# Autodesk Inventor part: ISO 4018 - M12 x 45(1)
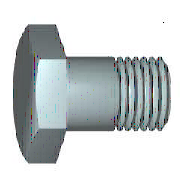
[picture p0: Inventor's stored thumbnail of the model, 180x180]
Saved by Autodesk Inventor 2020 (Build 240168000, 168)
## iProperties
Created: 2019-01
Part Number: ISO 4018 - M12 x 45(1)
Material: Ocel
Description: Šrouby se šestihrannou hlavou se závitem k hlavě. Výrobní třída C
Document SubType Name: Modeling
Standard: ISO 4018
Designer: doma
Standard Revision: Fourth edition 2011-04-01
Standards Organization: ISO
Language: cs-CZ
Size Designation: M12 x 45
Categories: <MemberInstance><Categories><Category DisplayName="Spojovací materiál" InternalName="e4da775c-781d-43d5-af7c-5136215cf5a6" Mnemonic="FSTN"><Category DisplayName
Density: 7.85 g/cm^3
Appearance: Plech
Mass: 56.3374 g
Surface Area: 26.8228 cm^2
Volume: 7.17674 cm^3
IsCustomPart: 0
Author: doma
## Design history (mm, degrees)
node "WorkPlane1"
node "WorkPoint1"
node "MSC_A1"
node "MSC_PF1"
node "MSC_PT1"
body "Solid1"
node "Náčrt1"
sketch "Náčrt2"
  geometry: L1 (-9, 5.196)-(-9, -5.196); L2 (0, 10.392)-(-9, 5.196); L3 (9, 5.196)-(0, 10.392); L4 (9, -5.196)-(9, 5.196); L5 (0, -10.392)-(9, -5.196); L6 (-9, -5.196)-(0, -10.392); C1 r 9 at (0, 0); 1 further point
  constraints: 12 end point, 6 tangent, 2 parallel, 2 vertical, 1 centre point
  dimensions: "d1" = 18 diameter of C1 (= ParS); "d29" = 0 distance of point (0, 0) C1.centre; "d30" = 0 distance of C1.centre point (0, 0)
extrude "Vysunutí1" new body sketch "Náčrt2" distance "d6" = 7.5 (= ParK); taper "d7" = 0 deg
revolve "Rotace1" stored, may be unused: angle "d14" = 360 deg
revolve "Rotace2" stored, may be unused: angle "d21" = 360 deg
chamfer "Zkosení1" distance "d22" = 0.875 (= 0.5 x PTC); stored, may be unused: second distance "d23" = 0.875 (= 0.5 x PTC), angle "d39" = 45 deg
fillet "Zaoblení1" dims "d24" = 0.6 (= r)
feature "Závit1" dims "d32" = 0, "b" = 41.5 (= NLG - 2 x PTC)
sketch "Náčrt3"
  geometry: L1 (9, 7.5)-(10.492, 7.5); L2 (10.492, 6.639)-(9, 7.5); L3 (10.492, 7.5)-(10.492, 6.639); L4 (0, -1.5)-(0, 9) reference; L5 (10.392, 0)-(10.392, 7.5) reference
  constraints: 6 end point, 1 horizontal, 1 vertical
  dimensions: "d25" = 0.1 distance between parallel lines of L5 L3; "d26" = 0 distance from line of L5.end L1; "d27" = 60 deg angle of L3 L2; "d28" = 9 distance from line of L4 L1.start (= 0.5 x ParS)
sketch "Náčrt4"
  geometry: L1 (0, -45)-(0, 0); L2 (-6, -45)-(0, -45); L3 (-6, 0)-(-6, -45); L4 (0, 0)-(-6, 0); L5 (0, -45)-(0, 0); L6 (-7.2, 0)-(1.2, 0) reference; L7 (0, -54)-(0, 9) reference
  constraints: 10 end point, 2 horizontal, 2 vertical
  dimensions: "d18" = 6 distance of L1.start L2.start (= 0.5 x NND); "d20" = 45 distance of L3.start L2.start (= NLG); "d33" = 0 distance between parallel lines of L7 L1; "d34" = 0 distance between parallel lines of L6 L4
other parameters: "NND" = 12 [user parameter; used in 2 equation terms], "NLG" = 45 [user parameter; used in 2 equation terms], "PTC" = 1.75 [user parameter; used in 3 equation terms], "ParK" = 7.5 [user parameter; used in 1 equation term], "ParS" = 18 [user parameter; used in 3 equation terms], "msp_es" = 10.39261 (= 0.577367 x ParS) [user parameter], "r" = 0.6 [user parameter; used in 1 equation term], "d2" = 15 (derived), "d4" = 17.32102 (derived), "d8" = 15 (derived), "d10" = 0 (derived), "d12" = 30 deg (derived), "d15" = 0 (derived), "d37" = 0, "d38" = 0, "d40" = 0, "d41" = 0, "d42" = 0, "THREADDIA" = 12 (= NND) [user parameter]
